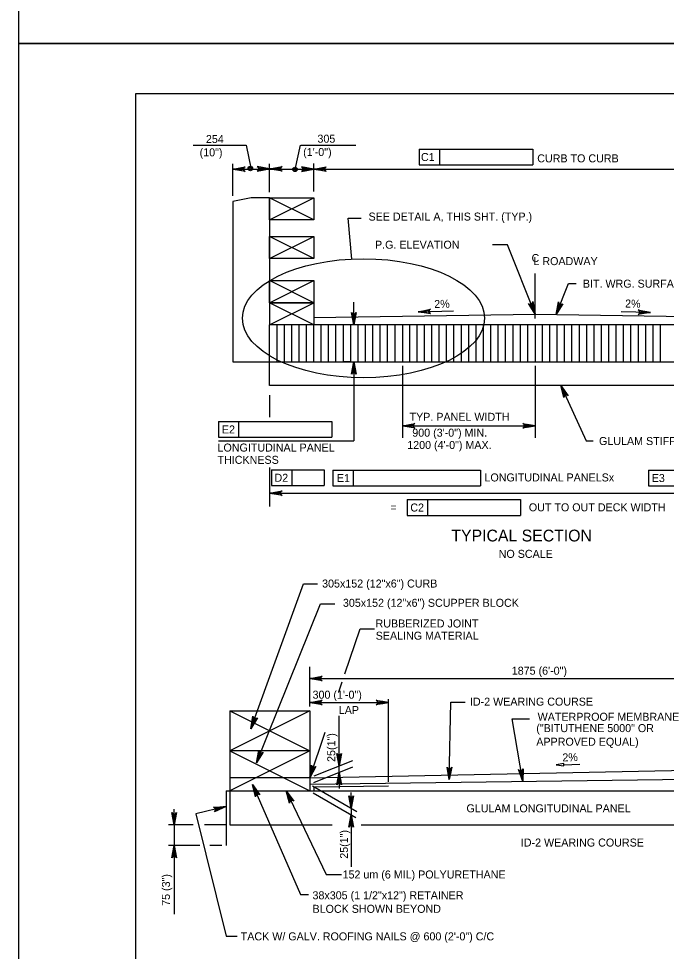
# Model space of a CAD drawing. Extents: x -8 to 75, y -110 to 0.
# Drawn here: x 0 to 9.71, y -79.61 to -65.62 of the extents above; entities that cross this region are included whole.
import ezdxf

# ---------------------------------------------------------------- set-up
doc = ezdxf.new("R2010")
doc.units = 0
for name, color, linetype in [('1', 7, 'Continuous'), ('2', 7, 'Continuous'), ('3', 7, 'Continuous'), ('4', 7, 'Continuous'), ('62', 7, 'Continuous'), ('63', 7, 'Continuous'), ('7', 7, 'Continuous')]:
    doc.layers.add(name, color=color, linetype=linetype)

msp = doc.modelspace()

# ---------------------------------------------------------------- linework, layer by layer
at = {"layer": '1'}
msp.add_lwpolyline([(1.75, -87.25), (33.25, -87.25), (33.25, -66.75), (1.75, -66.75)], close=True, dxfattribs=at)
at = {"layer": '2'}
for p, q in [((5.989, -70.019), (6.521, -70.005)), ((9.472, -70.032), (9.032, -70.019)), ((8.173, -76.813), (8.411, -76.807))]:
    msp.add_line(p, q, dxfattribs=at)
msp.add_lwpolyline([(8.174, -76.832), (8.173, -76.794), (8.06, -76.816)], close=True, dxfattribs=at)
at = {"layer": '3'}
for p, q in [((3.486, -68.31), (3.21, -68.365)), ((3.21, -68.365), (3.21, -70.769)), ((3.762, -68.31), (3.486, -68.31)), ((3.762, -68.31), (3.762, -70.217)), ((3.762, -68.31), (4.426, -68.31)), ((3.762, -68.641), (4.426, -68.31)), ((4.426, -68.641), (3.762, -68.31)), ((3.762, -68.641), (3.762, -68.31)), ((4.426, -68.31), (4.426, -68.641)), ((4.426, -68.641), (3.762, -68.641)), ((4.426, -69.222), (3.762, -68.89)), ((3.762, -69.222), (4.426, -68.89)), ((3.762, -69.222), (3.762, -68.89)), ((3.762, -68.89), (4.426, -68.89)), ((4.426, -68.89), (4.426, -69.222)), ((4.426, -69.222), (3.762, -69.222)), ((3.762, -69.885), (3.762, -69.553)), ((3.762, -69.885), (4.426, -69.553)), ((4.426, -69.885), (3.762, -69.553)), ((3.762, -69.553), (4.426, -69.553)), ((4.426, -69.553), (4.426, -69.885)), ((4.426, -69.885), (3.762, -69.885)), ((4.426, -70.217), (3.762, -69.885)), ((3.762, -70.217), (4.426, -69.885)), ((3.762, -69.885), (4.426, -69.885)), ((4.426, -69.885), (4.426, -70.217)), ((4.426, -70.106), (7.743, -70.056)), ((7.743, -70.056), (11.061, -70.106)), ((3.762, -70.769), (3.762, -70.217)), ((11.724, -70.217), (3.762, -70.217)), ((3.21, -70.769), (3.762, -70.769)), ((3.762, -71.124), (3.762, -70.769)), ((3.762, -70.769), (11.724, -70.769)), ((11.724, -71.124), (3.762, -71.124)), ((3.164, -76.004), (3.164, -77.716)), ((3.164, -76.004), (4.364, -76.004)), ((3.164, -76.004), (4.365, -76.604)), ((4.365, -76.004), (3.164, -76.604)), ((4.364, -76.004), (4.364, -77.204)), ((4.364, -76.604), (3.164, -76.604)), ((4.365, -76.604), (3.164, -77.204)), ((3.164, -76.604), (4.365, -77.204)), ((4.364, -77.008), (13.698, -76.821)), ((4.364, -77.008), (3.164, -77.008)), ((4.364, -77.106), (13.698, -76.982)), ((3.109, -77.204), (3.11, -78.025)), ((3.109, -77.204), (4.425, -77.204)), ((4.425, -77.146), (5.546, -77.131)), ((4.425, -77.146), (4.425, -77.204)), ((4.425, -77.204), (13.712, -77.204)), ((3.164, -77.716), (4.7, -77.716)), ((5.133, -77.716), (13.698, -77.716))]:
    msp.add_line(p, q, dxfattribs=at)
at = {"layer": '4'}
for p, q in [((2.615, -67.523), (3.409, -67.523)), ((3.409, -67.523), (3.487, -67.886)), ((4.22, -67.523), (4.142, -67.886)), ((4.231, -67.523), (5.053, -67.523)), ((6.005, -67.582), (7.706, -67.582)), ((6.005, -67.582), (6.005, -67.818)), ((6.307, -67.582), (6.307, -67.818)), ((7.706, -67.582), (7.706, -67.818)), ((3.21, -68.283), (3.21, -67.803)), ((3.762, -68.228), (3.762, -67.8)), ((4.426, -68.216), (4.426, -67.795)), ((6.005, -67.818), (7.706, -67.818)), ((3.21, -67.88), (12.277, -67.88)), ((4.994, -69.23), (4.938, -68.618)), ((4.938, -68.618), (5.135, -68.618)), ((7.33, -69.015), (7.102, -69.015)), ((7.743, -70.056), (7.33, -69.015)), ((7.743, -70.123), (7.743, -69.449)), ((8.056, -70.06), (8.244, -69.597)), ((8.244, -69.597), (8.358, -69.597)), ((5.026, -70.217), (5.026, -69.879)), ((4.97, -70.769), (4.863, -70.769)), ((5.026, -70.769), (5.026, -70.987)), ((5.752, -70.832), (5.752, -71.91)), ((7.743, -70.832), (7.743, -71.91)), ((5.026, -70.987), (5.026, -71.956)), ((8.13, -71.124), (8.505, -71.954)), ((3.762, -71.272), (3.762, -71.603)), ((2.995, -71.667), (4.696, -71.667)), ((2.995, -71.667), (2.995, -71.903)), ((3.297, -71.667), (3.297, -71.903)), ((4.696, -71.667), (4.696, -71.903)), ((5.752, -71.73), (7.743, -71.73)), ((2.995, -71.903), (4.696, -71.903)), ((2.995, -71.956), (5.026, -71.956)), ((8.505, -71.954), (8.614, -71.954)), ((3.762, -72.358), (3.762, -72.942)), ((3.792, -72.392), (4.58, -72.392)), ((3.792, -72.392), (3.792, -72.628)), ((4.094, -72.392), (4.094, -72.628)), ((4.58, -72.392), (4.58, -72.628)), ((4.711, -72.395), (6.922, -72.395)), ((4.711, -72.395), (4.711, -72.632)), ((5.013, -72.395), (5.013, -72.632)), ((6.922, -72.395), (6.922, -72.632)), ((9.443, -72.395), (11.143, -72.395)), ((9.443, -72.395), (9.443, -72.632)), ((3.792, -72.628), (4.58, -72.628)), ((4.711, -72.632), (6.922, -72.632)), ((9.443, -72.632), (11.143, -72.632)), ((3.762, -72.739), (11.724, -72.739)), ((5.824, -72.838), (7.525, -72.838)), ((5.824, -72.838), (5.824, -73.075)), ((6.127, -72.838), (6.127, -73.075)), ((7.525, -72.838), (7.525, -73.075)), ((5.824, -73.075), (7.525, -73.075)), ((4.269, -74.102), (4.482, -74.102)), ((4.526, -74.4), (4.739, -74.4)), ((5.119, -74.776), (5.333, -74.776)), ((4.364, -75.942), (4.364, -75.344)), ((4.364, -75.522), (11.746, -75.522)), ((4.364, -75.881), (5.546, -75.881)), ((5.546, -77.069), (5.546, -75.828)), ((6.48, -75.874), (6.694, -75.874)), ((4.804, -76.718), (4.804, -76.08)), ((7.397, -76.123), (7.658, -76.123)), ((4.432, -76.98), (5.012, -76.748)), ((4.425, -77.082), (5.012, -76.846)), ((4.804, -76.934), (4.804, -76.836)), ((4.804, -77.052), (4.804, -77.17)), ((3.506, -77.109), (4.225, -78.759)), ((4.012, -77.204), (4.609, -78.461)), ((4.404, -77.129), (5.068, -77.514)), ((4.414, -77.233), (5.056, -77.605)), ((4.984, -77.347), (4.984, -77.229)), ((2.331, -77.598), (2.331, -77.48)), ((4.984, -77.465), (4.984, -77.564)), ((2.617, -77.716), (2.247, -77.716)), ((2.331, -77.716), (2.331, -78.025)), ((3.102, -77.716), (2.785, -77.716)), ((4.984, -77.682), (4.984, -78.342)), ((2.714, -78.025), (2.247, -78.025)), ((3.048, -78.025), (2.866, -78.025)), ((2.331, -78.143), (2.331, -79.055)), ((4.609, -78.461), (4.842, -78.461)), ((4.225, -78.759), (4.347, -78.759))]:
    msp.add_line(p, q, dxfattribs=at)
for points in [[(3.21, -67.88), (3.396, -67.845), (3.382, -67.855), (3.374, -67.867), (3.372, -67.88), (3.374, -67.892), (3.382, -67.905), (3.396, -67.915), (3.21, -67.88), (3.382, -67.905), (3.374, -67.892), (3.21, -67.88), (3.372, -67.88), (3.374, -67.867), (3.21, -67.88), (3.382, -67.855)], [(3.762, -67.879), (3.576, -67.844), (3.59, -67.854), (3.598, -67.867), (3.6, -67.879), (3.598, -67.892), (3.59, -67.904), (3.576, -67.914), (3.762, -67.879), (3.59, -67.904), (3.598, -67.892), (3.762, -67.879), (3.6, -67.879), (3.598, -67.867), (3.762, -67.879), (3.59, -67.854)], [(3.762, -67.879), (3.949, -67.844), (3.934, -67.854), (3.927, -67.867), (3.925, -67.879), (3.927, -67.892), (3.934, -67.904), (3.949, -67.914), (3.762, -67.879), (3.934, -67.904), (3.927, -67.892), (3.762, -67.879), (3.925, -67.879), (3.927, -67.867), (3.762, -67.879), (3.934, -67.854)], [(4.426, -67.88), (4.239, -67.845), (4.254, -67.855), (4.261, -67.867), (4.263, -67.88), (4.261, -67.892), (4.254, -67.905), (4.239, -67.915), (4.426, -67.88), (4.254, -67.905), (4.261, -67.892), (4.426, -67.88), (4.263, -67.88), (4.261, -67.867), (4.426, -67.88), (4.254, -67.855)], [(4.426, -67.88), (4.612, -67.845), (4.598, -67.855), (4.59, -67.867), (4.588, -67.88), (4.59, -67.892), (4.598, -67.905), (4.612, -67.915), (4.426, -67.88), (4.598, -67.905), (4.59, -67.892), (4.426, -67.88), (4.588, -67.88), (4.59, -67.867), (4.426, -67.88), (4.598, -67.855)], [(7.743, -70.056), (7.642, -69.895), (7.656, -69.905), (7.671, -69.907), (7.683, -69.905), (7.694, -69.898), (7.703, -69.886), (7.707, -69.869), (7.743, -70.056), (7.703, -69.886), (7.694, -69.898), (7.743, -70.056), (7.683, -69.905), (7.671, -69.907), (7.743, -70.056), (7.656, -69.905)], [(8.056, -70.06), (8.094, -69.874), (8.098, -69.891), (8.106, -69.903), (8.117, -69.91), (8.13, -69.912), (8.144, -69.91), (8.159, -69.901), (8.056, -70.06), (8.144, -69.91), (8.13, -69.912), (8.056, -70.06), (8.117, -69.91), (8.106, -69.903), (8.056, -70.06), (8.098, -69.891)], [(5.026, -70.217), (4.991, -70.03), (5.001, -70.045), (5.014, -70.052), (5.026, -70.054), (5.039, -70.052), (5.051, -70.045), (5.061, -70.03), (5.026, -70.217), (5.051, -70.045), (5.039, -70.052), (5.026, -70.217), (5.026, -70.054), (5.014, -70.052), (5.026, -70.217), (5.001, -70.045)], [(5.989, -70.019), (6.174, -69.979), (6.16, -69.989), (6.153, -70.002), (6.151, -70.015), (6.154, -70.027), (6.162, -70.039), (6.176, -70.049), (5.989, -70.019), (6.162, -70.039), (6.154, -70.027), (5.989, -70.019), (6.151, -70.015), (6.153, -70.002), (5.989, -70.019), (6.16, -69.989)], [(9.472, -70.032), (9.285, -70.061), (9.3, -70.052), (9.307, -70.04), (9.31, -70.027), (9.308, -70.015), (9.301, -70.002), (9.287, -69.992), (9.472, -70.032), (9.301, -70.002), (9.308, -70.015), (9.472, -70.032), (9.31, -70.027), (9.307, -70.04), (9.472, -70.032), (9.3, -70.052)], [(5.026, -70.769), (5.061, -70.956), (5.051, -70.942), (5.039, -70.934), (5.026, -70.932), (5.014, -70.934), (5.001, -70.942), (4.991, -70.956), (5.026, -70.769), (5.001, -70.942), (5.014, -70.934), (5.026, -70.769), (5.026, -70.932), (5.039, -70.934), (5.026, -70.769), (5.051, -70.942)], [(8.13, -71.124), (8.238, -71.279), (8.223, -71.27), (8.209, -71.269), (8.197, -71.272), (8.186, -71.279), (8.178, -71.291), (8.175, -71.308), (8.13, -71.124), (8.178, -71.291), (8.186, -71.279), (8.13, -71.124), (8.197, -71.272), (8.209, -71.269), (8.13, -71.124), (8.223, -71.27)], [(5.752, -71.73), (5.939, -71.695), (5.924, -71.705), (5.917, -71.718), (5.915, -71.73), (5.917, -71.743), (5.924, -71.755), (5.939, -71.765), (5.752, -71.73), (5.924, -71.755), (5.917, -71.743), (5.752, -71.73), (5.915, -71.73), (5.917, -71.718), (5.752, -71.73), (5.924, -71.705)], [(7.743, -71.73), (7.557, -71.765), (7.571, -71.755), (7.579, -71.743), (7.581, -71.73), (7.579, -71.718), (7.571, -71.705), (7.557, -71.695), (7.743, -71.73), (7.571, -71.705), (7.579, -71.718), (7.743, -71.73), (7.581, -71.73), (7.579, -71.743), (7.743, -71.73), (7.571, -71.755)], [(3.762, -72.739), (3.949, -72.704), (3.934, -72.714), (3.927, -72.727), (3.925, -72.739), (3.927, -72.752), (3.934, -72.764), (3.949, -72.774), (3.762, -72.739), (3.934, -72.764), (3.927, -72.752), (3.762, -72.739), (3.925, -72.739), (3.927, -72.727), (3.762, -72.739), (3.934, -72.714)], [(3.481, -76.273), (4.269, -74.102)], [(3.564, -76.786), (4.526, -74.4)], [(4.891, -75.449), (5.119, -74.776)], [(4.364, -75.522), (4.551, -75.487), (4.537, -75.497), (4.529, -75.509), (4.527, -75.522), (4.529, -75.534), (4.537, -75.547), (4.551, -75.557), (4.364, -75.522), (4.537, -75.547), (4.529, -75.534), (4.364, -75.522), (4.527, -75.522), (4.529, -75.509), (4.364, -75.522), (4.537, -75.497)], [(4.801, -75.718), (4.851, -75.569)], [(4.364, -75.881), (4.551, -75.846), (4.537, -75.856), (4.529, -75.869), (4.527, -75.881), (4.529, -75.894), (4.537, -75.906), (4.551, -75.916), (4.364, -75.881), (4.537, -75.906), (4.529, -75.894), (4.364, -75.881), (4.527, -75.881), (4.529, -75.869), (4.364, -75.881), (4.537, -75.856)], [(5.546, -75.881), (5.359, -75.916), (5.373, -75.906), (5.381, -75.894), (5.383, -75.881), (5.381, -75.869), (5.373, -75.856), (5.359, -75.846), (5.546, -75.881), (5.373, -75.856), (5.381, -75.869), (5.546, -75.881), (5.383, -75.881), (5.381, -75.894), (5.546, -75.881), (5.373, -75.906)], [(6.452, -77.037), (6.48, -75.874)], [(3.481, -76.273), (3.512, -76.085), (3.516, -76.102), (3.526, -76.114), (3.537, -76.12), (3.549, -76.122), (3.563, -76.119), (3.578, -76.109), (3.481, -76.273), (3.563, -76.119), (3.549, -76.122), (3.481, -76.273), (3.537, -76.12), (3.526, -76.114), (3.481, -76.273), (3.516, -76.102)], [(7.56, -77.063), (7.397, -76.123)], [(4.365, -77.008), (4.595, -76.327)], [(3.564, -76.786), (3.601, -76.6), (3.605, -76.617), (3.614, -76.629), (3.625, -76.635), (3.637, -76.638), (3.652, -76.636), (3.666, -76.626), (3.564, -76.786), (3.652, -76.636), (3.637, -76.638), (3.564, -76.786), (3.625, -76.635), (3.614, -76.629), (3.564, -76.786), (3.605, -76.617)], [(4.804, -76.831), (4.769, -76.645), (4.779, -76.659), (4.792, -76.666), (4.804, -76.669), (4.817, -76.666), (4.829, -76.659), (4.839, -76.645), (4.804, -76.831), (4.829, -76.659), (4.817, -76.666), (4.804, -76.831), (4.804, -76.669), (4.792, -76.666), (4.804, -76.831), (4.779, -76.659)], [(4.364, -77.008), (4.391, -76.82), (4.396, -76.837), (4.405, -76.848), (4.417, -76.854), (4.429, -76.856), (4.443, -76.853), (4.457, -76.842), (4.364, -77.008), (4.443, -76.853), (4.429, -76.856), (4.364, -77.008), (4.417, -76.854), (4.405, -76.848), (4.364, -77.008), (4.396, -76.837)], [(6.452, -77.037), (6.422, -76.85), (6.431, -76.864), (6.444, -76.872), (6.456, -76.874), (6.469, -76.873), (6.481, -76.865), (6.492, -76.851), (6.452, -77.037), (6.481, -76.865), (6.469, -76.873), (6.452, -77.037), (6.456, -76.874), (6.444, -76.872), (6.452, -77.037), (6.431, -76.864)], [(7.56, -77.063), (7.494, -76.886), (7.506, -76.898), (7.52, -76.903), (7.532, -76.903), (7.544, -76.899), (7.555, -76.89), (7.563, -76.874), (7.56, -77.063), (7.555, -76.89), (7.544, -76.899), (7.56, -77.063), (7.532, -76.903), (7.52, -76.903), (7.56, -77.063), (7.506, -76.898)], [(4.804, -76.93), (4.839, -77.116), (4.829, -77.102), (4.817, -77.094), (4.804, -77.092), (4.792, -77.094), (4.779, -77.102), (4.769, -77.116), (4.804, -76.93), (4.779, -77.102), (4.792, -77.094), (4.804, -76.93), (4.804, -77.092), (4.817, -77.094), (4.804, -76.93), (4.829, -77.102)], [(3.506, -77.109), (3.613, -77.266), (3.598, -77.257), (3.583, -77.255), (3.571, -77.258), (3.56, -77.265), (3.552, -77.277), (3.548, -77.294), (3.506, -77.109), (3.552, -77.277), (3.56, -77.265), (3.506, -77.109), (3.571, -77.258), (3.583, -77.255), (3.506, -77.109), (3.598, -77.257)], [(4.012, -77.204), (4.123, -77.358), (4.108, -77.349), (4.094, -77.348), (4.082, -77.351), (4.071, -77.359), (4.063, -77.371), (4.06, -77.388), (4.012, -77.204), (4.063, -77.371), (4.071, -77.359), (4.012, -77.204), (4.082, -77.351), (4.094, -77.348), (4.012, -77.204), (4.108, -77.349)], [(4.984, -77.466), (4.949, -77.279), (4.959, -77.294), (4.972, -77.301), (4.984, -77.303), (4.997, -77.301), (5.009, -77.294), (5.019, -77.279), (4.984, -77.466), (5.009, -77.294), (4.997, -77.301), (4.984, -77.466), (4.984, -77.303), (4.972, -77.301), (4.984, -77.466), (4.959, -77.294)], [(3.109, -77.441), (2.656, -77.551), (3.113, -79.383), (3.278, -79.383)], [(3.109, -77.441), (2.937, -77.519), (2.948, -77.506), (2.952, -77.492), (2.952, -77.479), (2.947, -77.467), (2.936, -77.457), (2.92, -77.451), (3.109, -77.441), (2.936, -77.457), (2.947, -77.467), (3.109, -77.441), (2.952, -77.479), (2.952, -77.492), (3.109, -77.441), (2.948, -77.506)], [(2.331, -77.716), (2.296, -77.53), (2.306, -77.544), (2.319, -77.552), (2.331, -77.554), (2.344, -77.552), (2.356, -77.544), (2.366, -77.53), (2.331, -77.716), (2.356, -77.544), (2.344, -77.552), (2.331, -77.716), (2.331, -77.554), (2.319, -77.552), (2.331, -77.716), (2.306, -77.544)], [(4.985, -77.564), (5.02, -77.751), (5.01, -77.736), (4.997, -77.729), (4.985, -77.727), (4.972, -77.729), (4.96, -77.736), (4.95, -77.751), (4.985, -77.564), (4.96, -77.736), (4.972, -77.729), (4.985, -77.564), (4.985, -77.727), (4.997, -77.729), (4.985, -77.564), (5.01, -77.736)], [(2.331, -78.025), (2.366, -78.211), (2.356, -78.197), (2.344, -78.189), (2.331, -78.187), (2.319, -78.189), (2.306, -78.197), (2.296, -78.211), (2.331, -78.025), (2.306, -78.197), (2.319, -78.189), (2.331, -78.025), (2.331, -78.187), (2.344, -78.189), (2.331, -78.025), (2.356, -78.197)]]:
    msp.add_lwpolyline(points, dxfattribs=at)
for points in [[(8.158, -71.231), (8.191, -71.216), (8.13, -71.124)], [(5.872, -71.71), (5.872, -71.75), (5.752, -71.73)], [(7.623, -71.71), (7.623, -71.75), (7.743, -71.73)], [(4.483, -75.502), (4.483, -75.541), (4.364, -75.522)], [(4.483, -75.861), (4.483, -75.901), (4.364, -75.881)], [(5.428, -75.861), (5.428, -75.901), (5.546, -75.881)], [(3.481, -76.273), (3.484, -76.269), (3.482, -76.268)], [(3.564, -76.786), (3.567, -76.782), (3.565, -76.781)], [(4.784, -76.718), (4.823, -76.718), (4.804, -76.836)], [(4.364, -77.008), (4.367, -77.004), (4.365, -77.003)], [(4.784, -77.052), (4.823, -77.052), (4.804, -76.934)], [(6.452, -77.037), (6.454, -77.032), (6.451, -77.032)], [(7.56, -77.063), (7.55, -76.945), (7.53, -76.949)], [(3.506, -77.109), (3.507, -77.114), (3.509, -77.113)], [(4.012, -77.204), (4.013, -77.209), (4.015, -77.208)], [(3.109, -77.441), (3.105, -77.441), (3.105, -77.443)], [(4.965, -77.347), (5.004, -77.347), (4.984, -77.465)], [(2.312, -77.598), (2.351, -77.598), (2.331, -77.716)], [(4.965, -77.682), (5.004, -77.682), (4.984, -77.564)], [(2.312, -78.143), (2.351, -78.143), (2.331, -78.025)]]:
    msp.add_lwpolyline(points, close=True, dxfattribs=at)
for centre, radius in [((3.473, -67.873), 0.0333), ((3.473, -67.873), 0.0167), ((4.142, -67.886), 0.0333), ((4.142, -67.886), 0.0167)]:
    msp.add_circle(centre, radius, dxfattribs=at)
msp.add_ellipse((5.17, -70.118), major_axis=(1.815, 0), ratio=0.49188, dxfattribs=at)
at = {"layer": '62'}
msp.add_line((0, -66), (0, -66), dxfattribs=at)
at = {"layer": '63'}
for points in [[(0, -66), (34, -66), (34, -44), (0, -44)], [(0, -88), (34, -88), (34, -66), (0, -66)]]:
    msp.add_lwpolyline(points, close=True, dxfattribs=at)
at = {"layer": '7'}
for p, q in [((3.873, -70.769), (3.873, -70.217)), ((3.983, -70.769), (3.983, -70.217)), ((4.094, -70.769), (4.094, -70.217)), ((4.205, -70.769), (4.205, -70.217)), ((4.315, -70.769), (4.315, -70.217)), ((4.426, -70.769), (4.426, -70.217)), ((4.536, -70.769), (4.536, -70.217)), ((4.647, -70.769), (4.647, -70.217)), ((4.757, -70.769), (4.757, -70.217)), ((4.868, -70.769), (4.868, -70.217)), ((4.978, -70.769), (4.978, -70.217)), ((5.089, -70.769), (5.089, -70.217)), ((5.2, -70.769), (5.2, -70.217)), ((5.31, -70.769), (5.31, -70.217)), ((5.421, -70.769), (5.421, -70.217)), ((5.531, -70.769), (5.531, -70.217)), ((5.642, -70.769), (5.642, -70.217)), ((5.753, -70.217), (5.753, -70.769)), ((5.863, -70.769), (5.863, -70.217)), ((5.973, -70.769), (5.973, -70.217)), ((6.084, -70.769), (6.084, -70.217)), ((6.194, -70.769), (6.194, -70.217)), ((6.305, -70.769), (6.305, -70.217)), ((6.416, -70.769), (6.416, -70.217)), ((6.526, -70.769), (6.526, -70.217)), ((6.637, -70.769), (6.637, -70.217)), ((6.747, -70.769), (6.747, -70.217)), ((6.858, -70.769), (6.858, -70.217)), ((6.968, -70.769), (6.968, -70.217)), ((7.079, -70.769), (7.079, -70.217)), ((7.189, -70.769), (7.189, -70.217)), ((7.3, -70.769), (7.3, -70.217)), ((7.411, -70.769), (7.411, -70.217)), ((7.521, -70.769), (7.521, -70.217)), ((7.632, -70.769), (7.632, -70.217)), ((7.743, -70.217), (7.743, -70.769)), ((7.853, -70.769), (7.853, -70.217)), ((7.963, -70.769), (7.963, -70.217)), ((8.074, -70.769), (8.074, -70.217)), ((8.184, -70.769), (8.184, -70.217)), ((8.295, -70.769), (8.295, -70.217)), ((8.406, -70.769), (8.406, -70.217)), ((8.516, -70.769), (8.516, -70.217)), ((8.627, -70.769), (8.627, -70.217)), ((8.737, -70.769), (8.737, -70.217)), ((8.848, -70.769), (8.848, -70.217)), ((8.958, -70.769), (8.958, -70.217)), ((9.069, -70.769), (9.069, -70.217)), ((9.179, -70.769), (9.179, -70.217)), ((9.29, -70.769), (9.29, -70.217)), ((9.4, -70.769), (9.4, -70.217)), ((9.511, -70.769), (9.511, -70.217)), ((9.622, -70.769), (9.622, -70.217))]:
    msp.add_line(p, q, dxfattribs=at)

# ---------------------------------------------------------------- texts
at = {"layer": '4'}
for s, height, p in [('254', 0.12, (2.807, -67.49)), ('305', 0.12, (4.479, -67.485)), ('(10")', 0.12, (2.713, -67.69)), ('(1\'-0")', 0.12, (4.265, -67.685)), ('C1', 0.12, (6.031, -67.76)), ('CURB TO CURB', 0.12, (7.774, -67.78)), ('SEE DETAIL A, THIS SHT. (TYP.)', 0.12, (5.245, -68.653)), ('P.G. ELEVATION', 0.12, (5.342, -69.075)), ('C', 0.12, (7.689, -69.275)), ('L ROADWAY', 0.12, (7.717, -69.321)), ('BIT. WRG. SURFACE', 0.12, (8.458, -69.659)), ('TYP. PANEL WIDTH', 0.12, (5.86, -71.656)), ('E2', 0.12, (3.046, -71.845)), ('900 (3\'-0") MIN.', 0.12, (5.901, -71.894)), ('LONGITUDINAL PANEL', 0.12, (2.981, -72.117)), ('1200 (4\'-0") MAX.', 0.12, (5.825, -72.078)), ('GLULAM STIFFENER BEAM', 0.12, (8.7, -72.019)), ('THICKNESS', 0.12, (2.981, -72.301)), ('D2', 0.12, (3.835, -72.57)), ('LONGITUDINAL PANELSx', 0.12, (6.983, -72.565)), ('E1', 0.12, (4.771, -72.574)), ('E3', 0.12, (9.49, -72.574)), ('=', 0.12, (5.573, -73.013)), ('C2', 0.12, (5.871, -73.016)), ('OUT TO OUT DECK WIDTH', 0.12, (7.648, -73.013)), ('TYPICAL SECTION', 0.17717, (6.487, -73.465)), ('NO SCALE', 0.12, (7.196, -73.711)), ('305x152 (12"x6") CURB', 0.12, (4.549, -74.156)), ('305x152 (12"x6") SCUPPER BLOCK', 0.12, (4.861, -74.445)), ('RUBBERIZED JOINT', 0.12, (5.35, -74.755)), ('SEALING MATERIAL', 0.12, (5.352, -74.938)), ('1875 (6\'-0")', 0.12, (7.392, -75.463)), ('300 (1\'-0")', 0.12, (4.406, -75.823)), ('ID-2 WEARING COURSE', 0.12, (6.765, -75.927)), ('LAP', 0.12, (4.799, -76.053)), ('WATERPROOF MEMBRANE', 0.12, (7.78, -76.154)), ('("BITUTHENE 5000" OR', 0.12, (7.76, -76.324)), ('APPROVED EQUAL)', 0.12, (7.76, -76.528)), ('GLULAM LONGITUDINAL PANEL', 0.12, (6.713, -77.527)), ('ID-2 WEARING COURSE', 0.12, (7.528, -78.04)), ('152 um (6 MIL) POLYURETHANE', 0.12, (4.856, -78.519)), ('38x305 (1 1/2"x12") RETAINER', 0.12, (4.405, -78.831)), ('BLOCK SHOWN BEYOND', 0.12, (4.405, -79.034)), ('TACK W/ GALV. ROOFING NAILS @ 600 (2\'-0") C/C', 0.12, (3.329, -79.447))]:
    msp.add_text(s, height=height, dxfattribs=at).set_placement(p)
for s, rotation, p in [('2%', 1.5039, (6.231, -69.965)), ('2%', 358.4961, (9.09, -69.956)), ('25(1")', 90, (4.746, -76.771)), ('2%', 1.5039, (8.152, -76.764)), ('25(1")', 90, (4.937, -78.223)), ('75 (3")', 90, (2.268, -78.929))]:
    msp.add_text(s, height=0.12, rotation=rotation, dxfattribs=at).set_placement(p)

doc.saveas('drawing.dxf')
